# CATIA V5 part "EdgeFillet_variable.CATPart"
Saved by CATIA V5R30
Part number: Part1
Bounding box of the stored display mesh (mm): x -55 to 55, y -155 to 25.782, z -44.572 to 40
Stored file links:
  D:\PROJECTS\CATIA V56R 2020\Resources\Parts File\c17_catia_v6_6r2020_prt\EdgeFillet_variable.CATPart
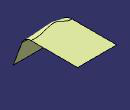
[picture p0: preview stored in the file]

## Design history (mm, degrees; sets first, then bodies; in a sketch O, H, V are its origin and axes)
Body1 (main body)
  Sketch1 on yz-plane, origin (0, 0, 0), H (0, 1, 0), V (0, 0, 1)
    point P1 (25.7818, 40)
    line L1 (25.7818, 40) -> (-124.2182, 40)
    line L2 (-124.2182, 40) -> (-155, -44.5723)
    point P3 (-155, -44.5723)
    length L1 = 150
    length L2 = 90
    angle L2 L1 = 110
    distance P1 H = 40
    distance P3 V = 155
    horizontal: L1 H
  Extrude1: Element1 Sketch1, Lim1 55, Lim2 55
  Plane1: type Offset, RefPlane yz-plane, Offset 20
  Point1: type OnCurve, Support edge [face of Extrude1 from Sketch1.L1 | face of Extrude1 from Sketch1.L2], Length 0
  Fillet1: radius 20, on edge [face of Extrude1 from Sketch1.L1 | face of Extrude1 from Sketch1.L2]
